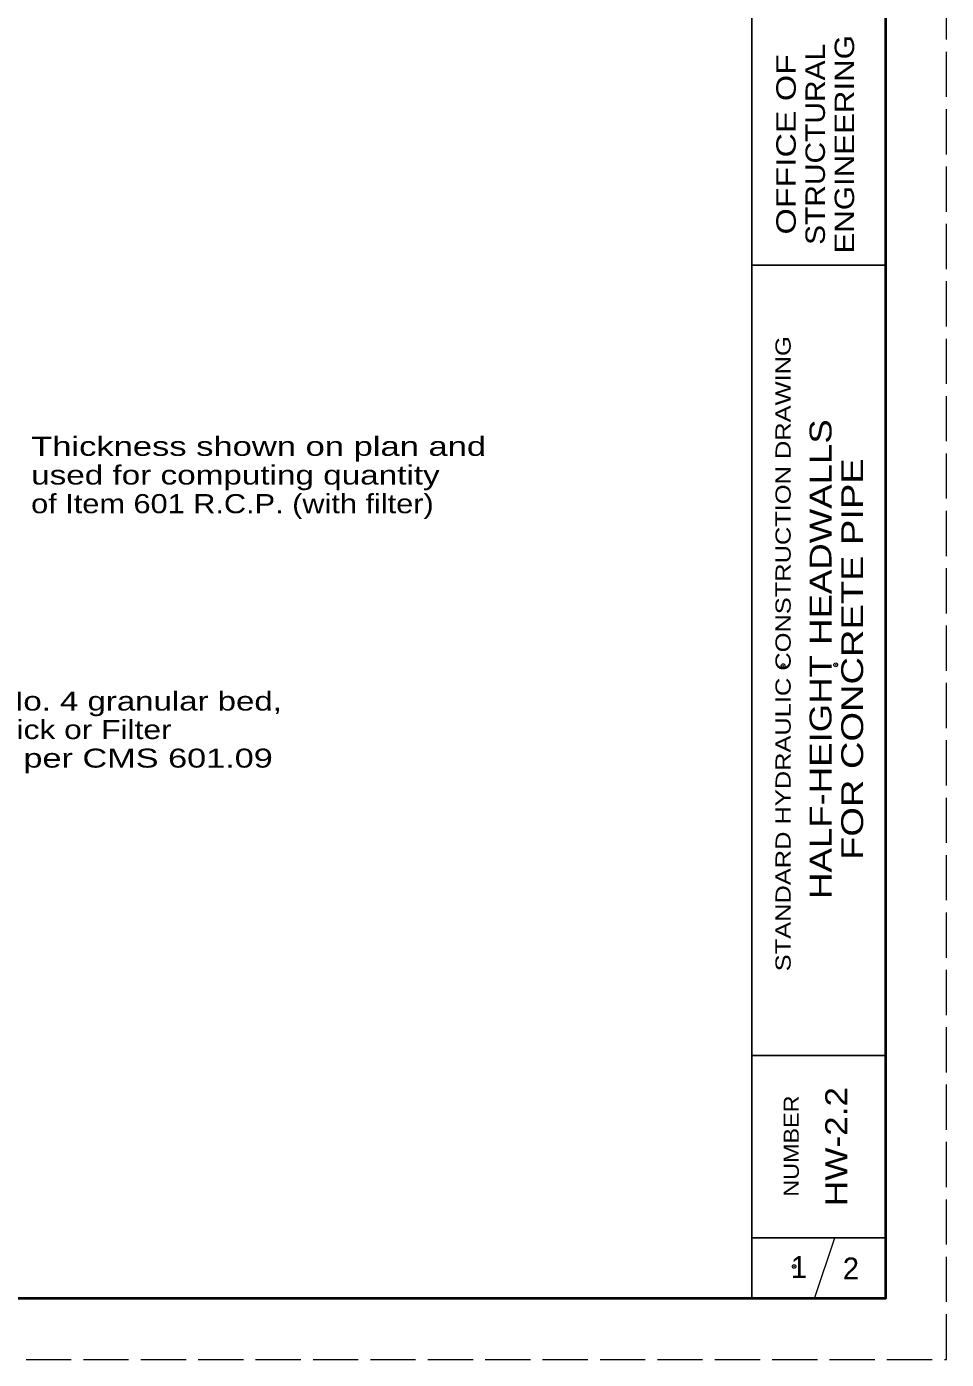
# Model space of a CAD drawing. Extents: x 685.4 to 719.4, y 1059.8 to 1105.8.
# Drawn here: x 711.88 to 719.44, y 1083.77 to 1094.73 of the extents above; entities that cross this region are included whole.
import ezdxf
from ezdxf.enums import TextEntityAlignment as Align

# ---------------------------------------------------------------- set-up
doc = ezdxf.new("R2010")
doc.units = 0
doc.header["$LTSCALE"] = 0.062
doc.header["$PDMODE"] = 32
doc.header["$PDSIZE"] = 0.031
doc.linetypes.add('LONG_DASHED', pattern=[7.5, 6, -1.5])
doc.layers.add('1', color=7, linetype='Continuous', lineweight=13)

msp = doc.modelspace()

# ---------------------------------------------------------------- linework, layer by layer
at = {"layer": '1', "lineweight": 25}
for p, q in [((717.84108, 1084.27067), (717.84108, 1105.27067)), ((718.94108, 1105.27067), (718.94108, 1084.27067)), ((718.94108, 1092.77067), (717.84108, 1092.77067)), ((718.94108, 1086.27067), (717.84108, 1086.27067)), ((718.94108, 1084.77067), (717.84108, 1084.77067))]:
    msp.add_line(p, q, dxfattribs=at)
at = {"layer": '1'}
msp.add_line((718.35775, 1084.27067), (718.52442, 1084.77067), dxfattribs=at)
at = {"layer": '1', "linetype": 'LONG_DASHED'}
msp.add_lwpolyline([(685.44108, 1083.77067), (719.44108, 1083.77067), (719.44108, 1105.77067), (685.44108, 1105.77067)], close=True, dxfattribs=at)
at = {"layer": '1', "lineweight": 25}
msp.add_lwpolyline([(718.94108, 1084.27067), (687.44108, 1084.27067), (687.44108, 1105.27067)], dxfattribs=at)
at = {"layer": '1', "lineweight": 40}
msp.add_lwpolyline([(687.44108, 1105.27067), (718.94108, 1105.27067), (718.94108, 1084.27067), (687.44108, 1084.27067)], close=True, dxfattribs=at)
at = {"layer": '1'}
for p in [(718.0985, 1089.47667), (718.53133, 1089.484), (718.18917, 1084.53442)]:
    msp.add_point(p, dxfattribs=at)

# ---------------------------------------------------------------- texts
for s, height, width, p in [('ENGINEERING', 0.16, 1.2, (718.68283, 1093.76521)), ('STRUCTURAL', 0.16, 1.15, (718.44283, 1093.76512)), ('OFFICE OF', 0.16, 1.3, (718.20283, 1093.76512)), ('STANDARD HYDRAULIC CONSTRUCTION DRAWING', 0.125, 1.25, (718.161, 1089.57471)), ('HALF-HEIGHT HEADWALLS', 0.18, 1.25, (718.49692, 1089.53079)), ('FOR CONCRETE PIPE', 0.18, 1.3, (718.75692, 1089.53083)), ('HW-2.2', 0.18, 1.2, (718.62558, 1085.52104)), ('NUMBER', 0.125, 1.15, (718.22808, 1085.52475))]:
    msp.add_text(s, height=height, rotation=90, dxfattribs=dict(at, width=width)).set_placement(p, align=Align.CENTER)
for s, height, width, p in [('Thickness shown on plan and', 0.1573, 1.35, (711.91525, 1091.20283)), ('used for computing quantity', 0.1573, 1.3, (711.91525, 1090.96683)), ('of Item 601 R.C.P. (with filter)', 0.1573, 1.2, (711.91525, 1090.73083)), ('No. 3 or No. 4 granular bed,', 0.156, 1.3, (710.61542, 1089.10758)), ('6" [150] thick or Filter', 0.156, 1.25, (710.61542, 1088.87292)), ('Fabric as per CMS 601.09', 0.156, 1.35, (710.61542, 1088.63825))]:
    msp.add_text(s, height=height, dxfattribs=dict(at, width=width)).set_placement(p)
for s, p in [('1', (718.22893, 1084.44075)), ('2', (718.65638, 1084.42817))]:
    msp.add_text(s, height=0.18, dxfattribs=at).set_placement(p, align=Align.CENTER)

doc.saveas('drawing.dxf')
